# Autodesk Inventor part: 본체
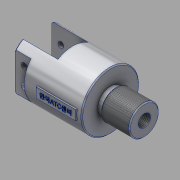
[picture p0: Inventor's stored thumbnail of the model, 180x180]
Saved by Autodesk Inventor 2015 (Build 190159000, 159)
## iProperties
Created: 2019-02
Part Number: 본체
Material: 알루미늄 6061
Document SubType Name: Modeling
Designer: SCD-A18
Density: 2.7 g/cm^3
Appearance: 알루미늄 - 평지
Mass: 345.893 g
Surface Area: 290.432 cm^2
Volume: 128.109 cm^3
Author: SCD-A18
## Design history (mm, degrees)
sketch "스케치1"
  geometry: L1 (-54, 0)-(54, 0); L2 (-54, 0)-(-54, 29); L3 (-54, 29)-(20, 29); L4 (20, 29)-(20, 13); L5 (20, 13)-(25, 13); L6 (25, 13)-(25, 15); L7 (25, 15)-(54, 15); L8 (54, 15)-(54, 0); 2 further points
  constraints: 16 end point, 4 perpendicular, 2 vertical, 1 coincident, 1 horizontal, 1 midpoint, 1 parallel
  dimensions: "d0" = 108 distance of L1.start L1.end; "d3" = 30 diameter of L7 L1; "d4" = 26 diameter of L5 L1; "d5" = 58 diameter of L3 L1; "d6" = 74 distance of L2.end L3.end; "d7" = 5 distance of L4.end L5.end
revolve "회전1" sketch "스케치1" stored, may be unused: angle "d8" = 90 deg
sketch "스케치2"
  geometry: L1 (54, 29)-(54, -29) reference; L2 (54, -29)-(-20, -29) reference; L3 (-20, -29)-(-20, -13) reference; L4 (-20, -13)-(-25, -13) reference; L5 (-25, -13)-(-25, -15) reference; L6 (-25, -15)-(-54, -15) reference; L7 (-54, -15)-(-54, 15) reference; L8 (-54, 15)-(-25, 15) reference; L9 (-25, 15)-(-25, 13) reference; L10 (-25, 13)-(-20, 13) reference; L11 (-20, 13)-(-20, 29) reference; L12 (-20, 29)-(54, 29) reference; L13 (54, 15)-(18, 15); L14 (18, 15)-(18, -15); L15 (18, -15)-(54, -15); L16 (54, -15)-(54, 15); L17 (54, 0)-(101.402, 0); L18 (54, 29)-(38, 29); L19 (38, 29)-(38, 22); L20 (38, 22)-(54, 22); L21 (54, 22)-(54, 29); L22 (38, -29)-(38, -22); L23 (38, -22)-(54, -22); L24 (54, -29)-(38, -29); L25 (54, -22)-(54, -29); 1 further point
  constraints: 26 end point, 4 parallel, 3 horizontal, 3 symmetric about line, 2 midpoint, 2 perpendicular
  dimensions: "d9" = 36 distance of L15.end L14.end; "d10" = 30 distance of L14.end L13.end; "d13" = 16 distance of L19.end L20.end; "d14" = 44 distance between parallel lines of L23 L20
extrude "돌출1" cut sketch "스케치2" stored distance "d11" = 113.5; taper "d12" = 0 deg
chamfer "모따기1" distance "d15" = 1; stored, may be unused: second distance "d16" = 2, angle "d17" = 45 deg
chamfer "모따기2" distance "d18" = 1; stored, may be unused: second distance "d19" = 2, angle "d20" = 45 deg
feature "스레드1" dims "d21" = 10, "d22" = 0
sketch "스케치3"
  geometry: L1 (20, -29)-(-18, -29) reference; L2 (-18, -29)-(-18, 29) reference; L3 (-18, 29)-(20, 29) reference; L4 (20, 29)-(20, 13) reference; L5 (20, 13)-(25, 13) reference; L6 (25, 13)-(25, 14) reference; L7 (25, 14)-(26, 15) reference; L8 (26, 15)-(53, 15) reference; L9 (53, 15)-(54, 14) reference; L10 (54, 14)-(54, -14) reference; L11 (54, -14)-(53, -15) reference; L12 (53, -15)-(26, -15) reference; L13 (26, -15)-(25, -14) reference; L14 (25, -14)-(25, -13) reference; L15 (25, -13)-(20, -13) reference; L16 (20, -13)-(20, -29) reference; L17 (-18, 14)-(-15.35, 14); L18 (-15.35, 14)-(-15.35, 17); L19 (-15.35, 17)-(-10.65, 17); L20 (-10.65, 17)-(-10.65, 14); L21 (-10.65, 14)-(-6.35, 14); L22 (-6.35, 14)-(-6.35, 17); L23 (-6.35, 17)-(-1.65, 17); L24 (-1.65, 17)-(-1.65, 14); L25 (-1.65, 14)-(2, 14); L26 (2, 14)-(2, 16); L27 (2, 16)-(9, 16); L28 (9, 16)-(9, 4); L29 (9, 4)-(54, 4); L30 (-18, 0)-(81.486, 0); L31 (-18, 14)-(-18, 0); L32 (-18, -24.819)-(-18, 24.819) reference; L33 (54, 4)-(54, 0); L34 (54, 0)-(-18, 0); L35 (-13, 17)-(-13, 30.361); L36 (-4, 17)-(-4, 31.286); 1 further point
  constraints: 38 end point, 10 point on line, 9 perpendicular, 5 midpoint, 3 horizontal, 2 vertical, 1 collinear
  dimensions: "d23" = 4.7 distance between parallel lines of L20 L18; "d24" = 4.7 distance of L22.end L23.end; "d25" = 34 diameter of L19 L30; "d26" = 28 diameter of L17 L30; "d27" = 5 distance from line of L35 L2.end; "d28" = 9 distance from line of L36 L35.end; "d29" = 32 diameter of L27 L30; "d30" = 20 distance between parallel lines of L2 L26; "d31" = 27 distance between parallel lines of L2 L28; "d32" = 8 diameter of L29 L30
revolve "회전2" sketch "스케치3" stored, may be unused: angle "d33" = 90 deg
hole "구멍1" diameter "d36" = 12.376; stored, may be unused: countersink angle "d40" = 90 deg, drill point angle "d42" = 120 deg; dims "d37" = 18, "d38" = 4, "d39" = 2, "d41" = 22, "d62" = 10, "d63" = 10
chamfer "모따기3" distance "d43" = 1; stored, may be unused: second distance "d44" = 2, angle "d45" = 45 deg
fillet "모깎기1" dims "d46" = 0.8
sketch "스케치4"
  geometry: L1 (54, -14)-(53, -15) reference; L2 (53, -15)-(26, -15) reference; L3 (26, -15)-(25, -14) reference; L4 (25, -14)-(25, -13) reference; L5 (25, -13)-(20, -13) reference; L6 (20, -13)-(20, -29) reference; L7 (20, -29)-(-18, -29) reference; L8 (-18, -29)-(-18, -15) reference; L9 (-18, -15)-(-17, -14) reference; L10 (-17, -14)-(-15.35, -14) reference; L11 (-15.35, -14)-(-15.35, -16.2) reference; L12 (-14.55, -17)-(-11.45, -17) reference; L13 (-10.65, -16.2)-(-10.65, -14) reference; L14 (-10.65, -14)-(-6.35, -14) reference; L15 (-6.35, -14)-(-6.35, -16.2) reference; L16 (-5.55, -17)-(-2.45, -17) reference; L17 (-1.65, -16.2)-(-1.65, -14) reference; L18 (-1.65, -14)-(2, -14) reference; L19 (2, -14)-(2, -16) reference; L20 (2, -16)-(9, -16) reference; L21 (9, -16)-(9, -4) reference; L22 (9, -4)-(30.737, -4) reference; L23 (30.737, -4)-(32, -6.188) reference; L24 (32, -6.188)-(54, -6.188) reference; L25 (54, -6.188)-(54, -14) reference; L26 (53, 15)-(54, 14) reference; L27 (54, 14)-(54, 6.188) reference; L28 (54, 6.188)-(32, 6.188) reference; L29 (32, 6.188)-(30.737, 4) reference; L30 (30.737, 4)-(9, 4) reference; L31 (9, 4)-(9, 16) reference; L32 (9, 16)-(2, 16) reference; L33 (2, 16)-(2, 14) reference; L34 (2, 14)-(-1.65, 14) reference; L35 (-1.65, 14)-(-1.65, 16.2) reference; L36 (-2.45, 17)-(-5.55, 17) reference; L37 (-6.35, 16.2)-(-6.35, 14) reference; L38 (-6.35, 14)-(-10.65, 14) reference; L39 (-10.65, 14)-(-10.65, 16.2) reference; L40 (-11.45, 17)-(-14.55, 17) reference; L41 (-15.35, 16.2)-(-15.35, 14) reference; L42 (-15.35, 14)-(-17, 14) reference; L43 (-17, 14)-(-18, 15) reference; L44 (-18, 15)-(-18, 29) reference; L45 (-18, 29)-(20, 29) reference; L46 (20, 29)-(20, 13) reference; L47 (20, 13)-(25, 13) reference; L48 (25, 13)-(25, 14) reference; L49 (25, 14)-(26, 15) reference; L50 (26, 15)-(53, 15) reference; L51 (-53, 24.819)-(-18, 24.819) reference; L52 (-54, -23.643)-(-54, 23.643) reference; L53 (-18, -24.819)-(-53, -24.819) reference; L54 (-45, 9)-(-45, -9); C1 r 3 at (-45, 9); C2 r 3 at (-45, -9); A1 r 0.8 centre (-14.55, -16.2) between (-15.35, -16.2) and (-14.55, -17) reference; A2 r 0.8 centre (-11.45, -16.2) between (-11.45, -17) and (-10.65, -16.2) reference; A3 r 0.8 centre (-5.55, -16.2) between (-6.35, -16.2) and (-5.55, -17) reference; A4 r 0.8 centre (-2.45, -16.2) between (-2.45, -17) and (-1.65, -16.2) reference; A5 r 0.8 centre (-2.45, 16.2) between (-1.65, 16.2) and (-2.45, 17) reference; A6 r 0.8 centre (-5.55, 16.2) between (-5.55, 17) and (-6.35, 16.2) reference; A7 r 0.8 centre (-11.45, 16.2) between (-10.65, 16.2) and (-11.45, 17) reference; A8 r 0.8 centre (-14.55, 16.2) between (-14.55, 17) and (-15.35, 16.2) reference; 2 further points
  constraints: 2 centre point, 2 end point, 1 equal radius, 1 horizontal alignment, 1 midpoint, 1 vertical, 1 vertical alignment
  dimensions: "d47" = 9 distance from line of L54.end L52; "d48" = 6 diameter of C2; "d49" = 18 distance of L54.start L54.end
extrude "돌출2" cut sketch "스케치4" stored distance "d50" = 113.5; taper "d51" = 0 deg
node "작업 평면1"
sketch "스케치5"
  geometry: L1 (-25, 5)-(15, 5); L2 (15, 5)-(15, -5); L3 (15, -5)-(-25, -5); L4 (-25, -5)-(-25, 5); L5 (20, -29)-(20, 29) reference; 2 further points
  constraints: 8 end point, 2 parallel, 1 horizontal, 1 horizontal alignment, 1 midpoint, 1 perpendicular
  dimensions: "d53" = 5 distance between parallel lines of L5 L2; "d54" = 40 distance of L1.start L1.end; "d55" = 10 distance of L3.end L1.start
extrude "돌출3" join sketch "스케치5" stored distance "d56" = 113.5; taper "d57" = 0 deg
sketch "스케치6"
  geometry: L1 (-25, -5)-(-25, 5) reference; L2 (15, -5)-(-25, -5) reference; 2 further points
  constraints: 1 other
  dimensions: "d58" = 20 distance from line of L1 point (-5, 0); "d59" = 5 distance from line of L2 point (-5, 0)
feature "엠보싱1" sketch "스케치6" dims "d60" = 0.5, "d61" = 0
chamfer "모따기4" distance "d64" = 1; stored, may be unused: second distance "d65" = 2, angle "d66" = 45 deg
node "솔리드1"
node "절단 모서리 투영1"
node "절단 모서리 투영2"
node "절단 모서리 투영3"
